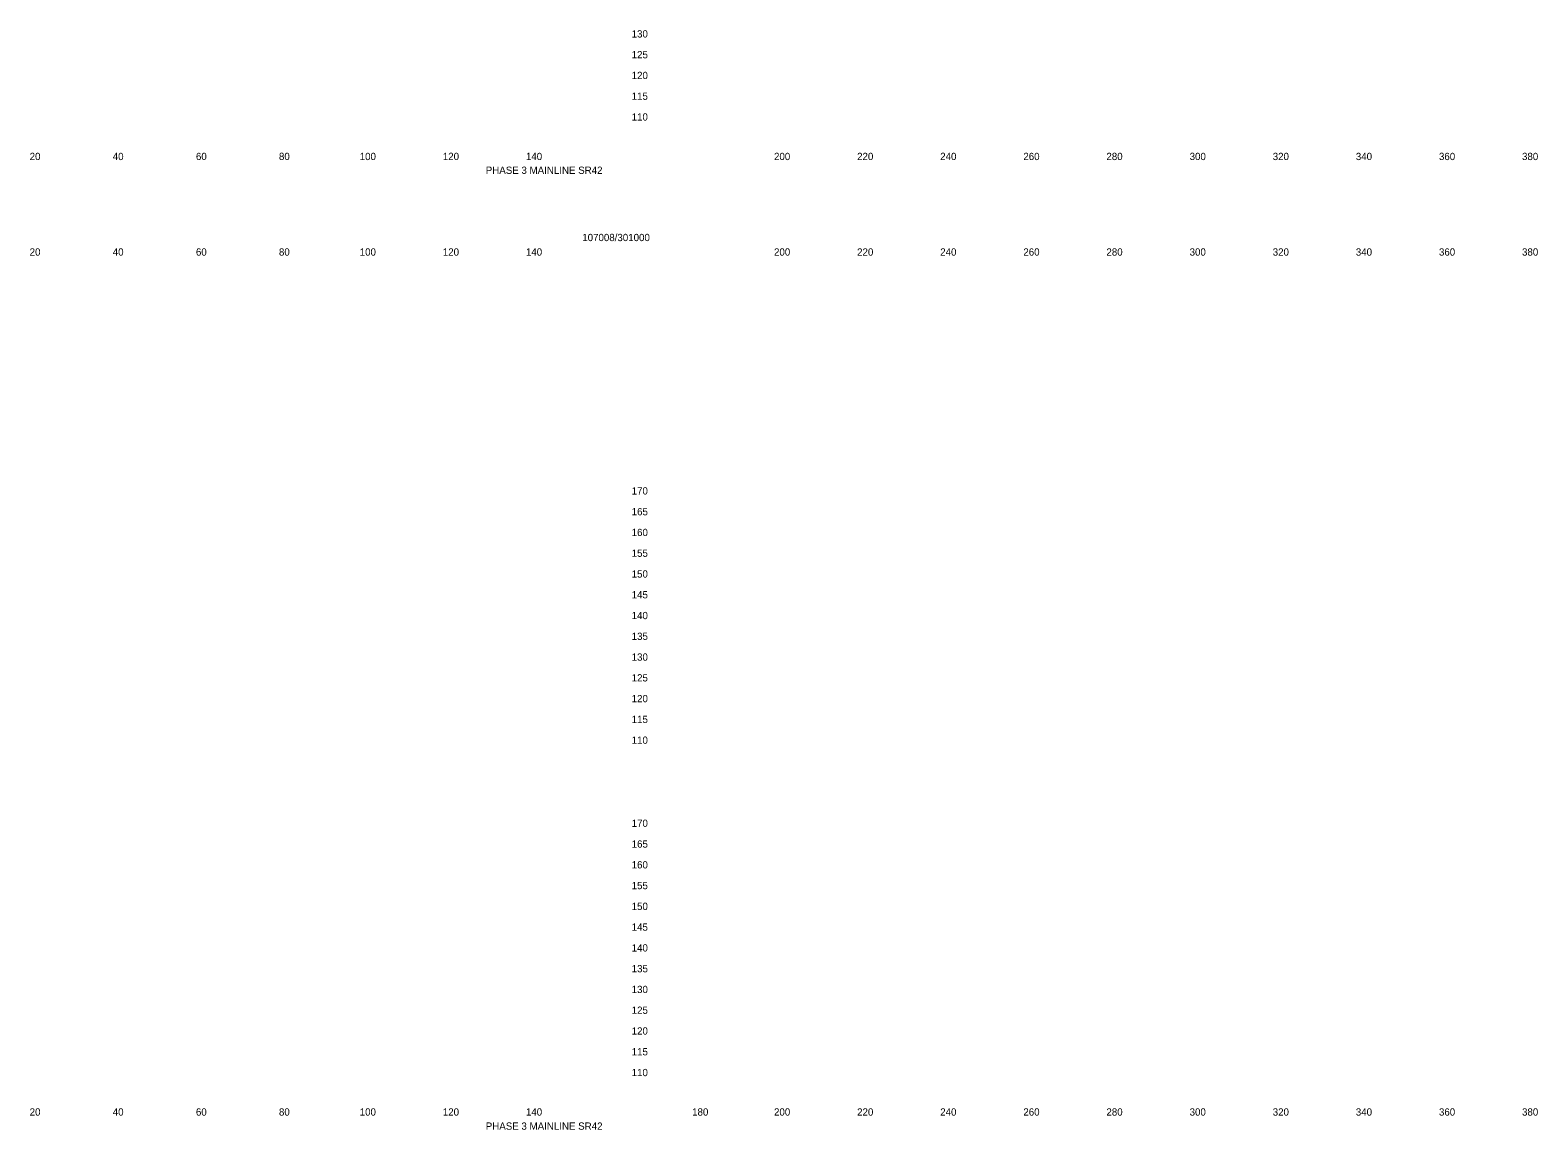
# Model space of a CAD drawing. Extents: x 21281 to 22024, y 6472 to 15198.
# Drawn here: x 21661.4 to 22024.2, y 10841.9 to 11106.6 of the extents above; entities that cross this region are included whole.
import ezdxf

# ---------------------------------------------------------------- set-up
doc = ezdxf.new("R2010")
doc.units = 0
doc.layers.add('Draft_XS_Grid', color=7, linetype='Continuous')
doc.layers.add('Draft_XS_Text', color=7, linetype='Continuous')

msp = doc.modelspace()

# ---------------------------------------------------------------- texts
at = {"layer": 'Draft_XS_Grid'}
for s, p in [('  130  ', (21804.84, 11104.84)), ('  125  ', (21804.84, 11099.84)), ('  120  ', (21804.84, 11094.84)), ('  115  ', (21804.84, 11089.84)), ('  110  ', (21804.84, 11084.84)), ('  170  ', (21804.84, 10994.84)), ('  165  ', (21804.84, 10989.84)), ('  160  ', (21804.84, 10984.84)), ('  155  ', (21804.84, 10979.84)), ('  150  ', (21804.84, 10974.84)), ('  145  ', (21804.84, 10969.84)), ('  140  ', (21804.84, 10964.84)), ('  135  ', (21804.84, 10959.84)), ('  130  ', (21804.84, 10954.84)), ('  125  ', (21804.84, 10949.84)), ('  120  ', (21804.84, 10944.84)), ('  115  ', (21804.84, 10939.84)), ('  110  ', (21804.84, 10934.84)), ('  170  ', (21804.84, 10914.84)), ('  165  ', (21804.84, 10909.84)), ('  160  ', (21804.84, 10904.84)), ('  155  ', (21804.84, 10899.84)), ('  150  ', (21804.84, 10894.84)), ('  145  ', (21804.84, 10889.84)), ('  140  ', (21804.84, 10884.84)), ('  135  ', (21804.84, 10879.84)), ('  130  ', (21804.84, 10874.84)), ('  125  ', (21804.84, 10869.84)), ('  120  ', (21804.84, 10864.84)), ('  115  ', (21804.84, 10859.84)), ('  110  ', (21804.84, 10854.84))]:
    msp.add_text(s, height=1.75, dxfattribs=at).set_placement(p)
at = {"layer": 'Draft_XS_Text'}
for s, p in [('  20  ', (21659.95, 11075.34)), ('  40  ', (21679.95, 11075.34)), ('  60  ', (21699.97, 11075.34)), ('  80  ', (21719.95, 11075.34)), ('  100  ', (21739.39, 11075.34)), ('  120  ', (21759.39, 11075.34)), ('  140  ', (21779.39, 11075.34)), ('  200  ', (21839.1, 11075.34)), ('  220  ', (21859.1, 11075.34)), ('  240  ', (21879.1, 11075.34)), ('  260  ', (21899.11, 11075.34)), ('  280  ', (21919.1, 11075.34)), ('  300  ', (21939.13, 11075.34)), ('  320  ', (21959.13, 11075.34)), ('  340  ', (21979.13, 11075.34)), ('  360  ', (21999.14, 11075.34)), ('  380  ', (22019.13, 11075.34)), ('PHASE 3 MAINLINE SR42', (21771.03, 11072.02)), ('107008/301000', (21794.25, 11055.83)), ('  20  ', (21659.95, 11052.34)), ('  40  ', (21679.95, 11052.34)), ('  60  ', (21699.97, 11052.34)), ('  80  ', (21719.95, 11052.34)), ('  100  ', (21739.39, 11052.34)), ('  120  ', (21759.39, 11052.34)), ('  140  ', (21779.39, 11052.34)), ('  200  ', (21839.1, 11052.34)), ('  220  ', (21859.1, 11052.34)), ('  240  ', (21879.1, 11052.34)), ('  260  ', (21899.11, 11052.34)), ('  280  ', (21919.1, 11052.34)), ('  300  ', (21939.13, 11052.34)), ('  320  ', (21959.13, 11052.34)), ('  340  ', (21979.13, 11052.34)), ('  360  ', (21999.14, 11052.34)), ('  380  ', (22019.13, 11052.34)), ('  20  ', (21659.95, 10845.34)), ('  40  ', (21679.95, 10845.34)), ('  60  ', (21699.97, 10845.34)), ('  80  ', (21719.95, 10845.34)), ('  100  ', (21739.39, 10845.34)), ('  120  ', (21759.39, 10845.34)), ('  140  ', (21779.39, 10845.34)), ('  180  ', (21819.39, 10845.34)), ('  200  ', (21839.1, 10845.34)), ('  220  ', (21859.1, 10845.34)), ('  240  ', (21879.1, 10845.34)), ('  260  ', (21899.11, 10845.34)), ('  280  ', (21919.1, 10845.34)), ('  300  ', (21939.13, 10845.34)), ('  320  ', (21959.13, 10845.34)), ('  340  ', (21979.13, 10845.34)), ('  360  ', (21999.14, 10845.34)), ('  380  ', (22019.13, 10845.34)), ('PHASE 3 MAINLINE SR42', (21771.03, 10841.94))]:
    msp.add_text(s, height=1.75, dxfattribs=at).set_placement(p)

doc.saveas('drawing.dxf')
